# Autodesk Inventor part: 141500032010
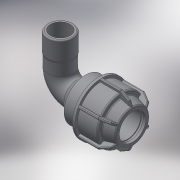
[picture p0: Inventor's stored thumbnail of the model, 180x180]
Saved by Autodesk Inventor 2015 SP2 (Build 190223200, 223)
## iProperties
Created: 2017-08
Part Number: 141500032010
Material: Generic
Description: L.14 90° ELBOW FEMALE ADAPTOR (SILVER) 32-1"
Document SubType Name: Modeling
Designer: KIM
Density: 1 g/cm^3
Appearance: Default
Author: KIM
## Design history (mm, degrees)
derived "141500.ipt"
feature "Solid1::141500.ipt"
feature "Solid2::141500.ipt"
tag "TaggingFeature1"
body "Solid1"
body "Solid2"
other parameters: "d1" = 32, "d2" = 56, "d4" = 15 deg, "d5" = 36.96, "d6" = 12.1968, "d10" = 61, "d16" = 32.64, "d17" = 2.8, "d22" = 51.2, "d24" = 2.8, "d25" = 54.9, "d26" = 45.75, "d27" = 2.8, "d28" = 135 deg, "d29" = 1.68, "d31" = 1.6, "d46" = 150 deg, "d49" = 3.05, "d50" = 0, "d58" = 0.96, "d61" = 360 deg, "d63" = 28.8, "d95" = 30.291, "d96" = 39.3783, "d97" = 21, "d98" = 24.2328, "d99" = 35.44047, "d100" = 135 deg, "d108" = 1.6, "d112" = 27.3, "d113" = 75, "d114" = 57.12, "d115" = 35.44047, "d116" = 45 deg, "d117" = 0, "d118" = 0, "d_" = 32, "G_" = 30.291, "E_" = 61, "A_" = 75, "l_" = 56, "l_2" = 21
